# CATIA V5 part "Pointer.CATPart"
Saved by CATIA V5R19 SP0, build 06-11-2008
Part number: Follower
Bounding box of the stored display mesh (mm): x -9.942 to 9.942, y -9.942 to 9.942, z 0 to 100
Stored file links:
  D:\Shriniwas\v5_r19\c16_CAT_v5r19\c16_Part\Cam_Follower_msm_trial\Pointer.CATPart
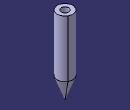
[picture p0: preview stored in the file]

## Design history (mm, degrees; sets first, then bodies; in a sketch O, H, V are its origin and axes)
Body1 (main body)
  Sketch1 on yz-plane, origin (0, 0, 0), H (0, 1, 0), V (0, 0, 1)
    line L1 (0, 0) -> (10, 27.4748)
    point P1 (10, 27.4748)
    line L2 (10, 27.4748) -> (10, 100)
    point P2 (10, 27.4748)
    point P3 (10, 100)
    point P4 (0, 100)
    point P5 (10, 91.3901)
    line L3 (0, 0) -> (0, 100)
    reference intersected line E1 through (0, 0) direction (-1, 0) from xy-plane
    reference intersected line E3 through (0, 0) direction (0, 1) from zx-plane
    line L4 (0, 100) -> (10, 100)
    point P6 (10, 100)
    angle L1 L3 = 20
    distance O P4 = 100
    length L4 = 10
    coincidence: P2 L1, P4 V, P5 L2, P2 P1, E3 P4, P1 L2, P6 L2, P6 P3
    vertical: L2 V, L3 V, E3 V
    horizontal: E1 H, L4 H
    perpendicularity: E1 L2
  Shaft1: profile Sketch1, axis Sketch1.L3, angle 360
  Sketch2 on face of Shaft1 from Sketch1.L4, origin (0, 0, 100), H (1, 0, 0), V (0, 1, 0)
    point P1 (0, 0)
  Hole1: placed by Sketch2, at (0, 0, 100) direction (0, 0, -1), diameter 10, depth 55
